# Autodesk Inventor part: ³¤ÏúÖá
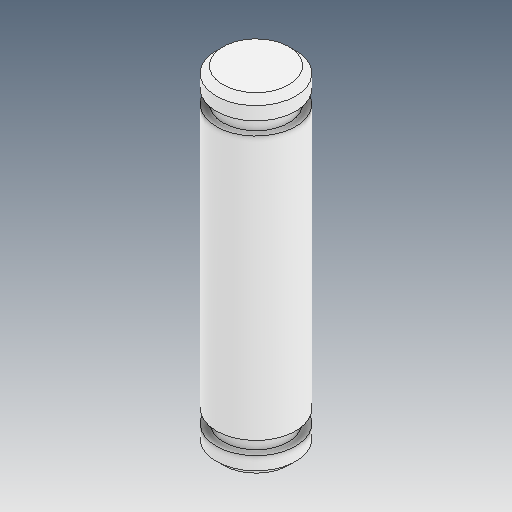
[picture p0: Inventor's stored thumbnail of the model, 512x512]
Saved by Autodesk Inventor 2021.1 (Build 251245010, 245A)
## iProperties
Created: 2021-06
Part Number: ³¤ÏúÖá
Material: Ogólny
Document SubType Name: Modeling
Designer: user
Density: 1 g/cm^3
Appearance: Domyślna
Author: user
Revision Number: ÈÎºÎ
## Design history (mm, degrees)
feature "ÊäÈë1"
node "Bryła1"
